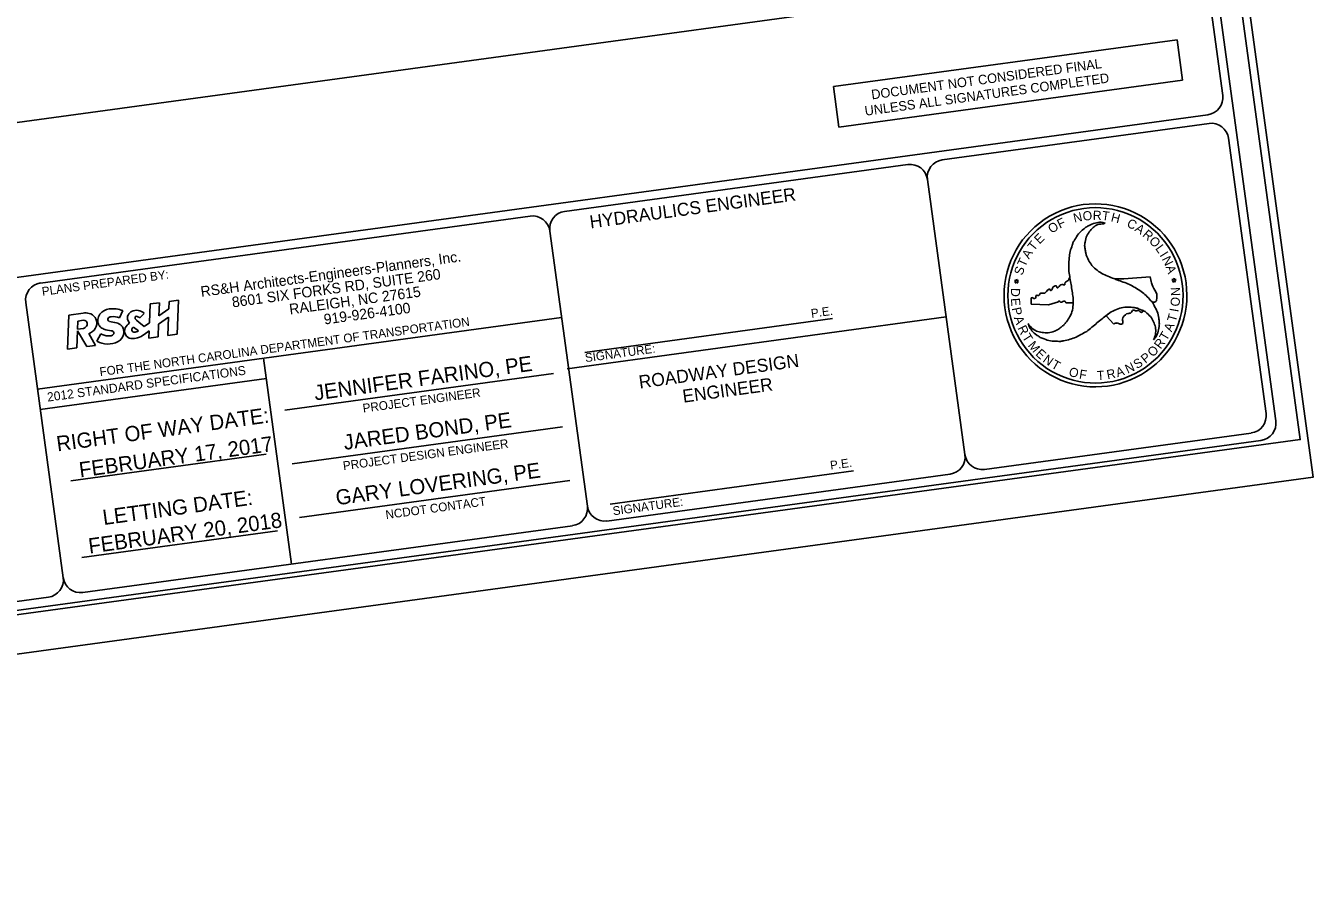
# Model space of a CAD drawing. Extents: x 2110583 to 2112764, y 580993 to 582575.
# Drawn here: x 2111873 to 2112764, y 580993 to 581578 of the extents above; entities that cross this region are included whole.
import ezdxf

# ---------------------------------------------------------------- set-up
doc = ezdxf.new("R2010")
doc.units = 0
for name, color, linetype in [('Default', 7, 'Continuous'), ('Sheet Data Field CELL', 7, 'Continuous'), ('Sheet Plot Border Inside CELL', 7, 'Continuous'), ('Sheet Plot Border Outside CELL', 7, 'Continuous'), ('Sheet Sticker Exception Certification CELL', 7, 'Continuous'), ('Sheet Title CELL', 7, 'Continuous')]:
    doc.layers.add(name, color=color, linetype=linetype)

msp = doc.modelspace()

# ---------------------------------------------------------------- linework, layer by layer
at = {"layer": 'Default'}
for p, q in [((2111958.78, 581385.98), (2111965.29, 581386.87)), ((2111965.29, 581386.87), (2111958.78, 581385.98)), ((2111965.29, 581386.87), (2111964.92, 581377.69)), ((2111964.92, 581377.69), (2111965.29, 581386.87)), ((2111971.81, 581382.67), (2111972.03, 581387.77)), ((2111972.03, 581387.77), (2111971.81, 581382.67)), ((2111972.03, 581387.77), (2111978.5, 581388.66)), ((2111978.5, 581388.66), (2111972.03, 581387.77)), ((2111978.5, 581388.66), (2111977.61, 581365.07)), ((2111977.61, 581365.07), (2111978.5, 581388.66)), ((2111901.51, 581354.72), (2111902.44, 581378.29)), ((2111902.44, 581378.29), (2111901.51, 581354.72)), ((2111902.44, 581378.29), (2111912.46, 581379.66)), ((2111912.46, 581379.66), (2111902.44, 581378.29)), ((2111937.71, 581376.35), (2111939.99, 581381.38)), ((2111954.76, 581379.5), (2111951.61, 581376.34)), ((2111951.61, 581376.34), (2111954.76, 581379.5)), ((2111958.3, 581372.99), (2111958.78, 581385.98)), ((2111958.78, 581385.98), (2111958.3, 581372.99)), ((2111964.92, 581377.69), (2111971.81, 581382.67)), ((2111971.81, 581382.67), (2111964.92, 581377.69)), ((2111908.52, 581368.56), (2111908.73, 581374.12)), ((2111908.52, 581368.56), (2111908.73, 581374.12)), ((2111912.58, 581369.12), (2111908.52, 581368.56)), ((2111912.58, 581369.12), (2111908.52, 581368.56)), ((2111908.73, 581374.12), (2111912.79, 581374.67)), ((2111908.73, 581374.12), (2111912.79, 581374.67)), ((2111950.65, 581367.45), (2111947.38, 581370.03)), ((2111947.38, 581370.03), (2111950.65, 581367.45)), ((2111949.4, 581374.78), (2111951.14, 581373.26)), ((2111951.14, 581373.26), (2111949.4, 581374.78)), ((2111951.09, 581373.31), (2111954.67, 581370.43)), ((2111951.14, 581373.26), (2111951.09, 581373.31)), ((2111954.67, 581370.43), (2111951.09, 581373.31)), ((2111951.09, 581373.31), (2111951.14, 581373.26)), ((2111954.67, 581370.43), (2111958.3, 581372.99)), ((2111958.3, 581372.99), (2111954.67, 581370.43)), ((2111964.68, 581372.07), (2111964.36, 581363.27)), ((2111964.36, 581363.27), (2111964.68, 581372.07)), ((2111971.6, 581376.96), (2111964.68, 581372.07)), ((2111964.68, 581372.07), (2111971.6, 581376.96)), ((2111971.04, 581364.18), (2111971.6, 581376.96)), ((2111971.6, 581376.96), (2111971.04, 581364.18)), ((2111908.46, 581367.49), (2111907.97, 581355.61)), ((2111907.97, 581355.61), (2111908.46, 581367.49)), ((2111914.88, 581356.5), (2111908.46, 581367.49)), ((2111908.46, 581367.49), (2111914.88, 581356.5)), ((2111916.35, 581365.44), (2111921.02, 581357.34)), ((2111921.02, 581357.34), (2111916.35, 581365.44)), ((2111924.78, 581365.21), (2111921.94, 581360.27)), ((2111925.63, 581364.83), (2111924.78, 581365.21)), ((2111928.19, 581368.2), (2111931.91, 581367.47)), ((2111958.04, 581367.31), (2111954.68, 581364.91)), ((2111954.68, 581364.91), (2111958.04, 581367.31)), ((2111957.8, 581362.37), (2111958.04, 581367.31)), ((2111958.04, 581367.31), (2111957.8, 581362.37)), ((2111964.36, 581363.27), (2111957.8, 581362.37)), ((2111957.8, 581362.37), (2111964.36, 581363.27)), ((2111977.61, 581365.07), (2111971.04, 581364.18)), ((2111971.04, 581364.18), (2111977.61, 581365.07)), ((2111907.97, 581355.61), (2111901.51, 581354.72)), ((2111901.51, 581354.72), (2111907.97, 581355.61)), ((2111921.02, 581357.34), (2111914.88, 581356.5)), ((2111914.88, 581356.5), (2111921.02, 581357.34))]:
    msp.add_line(p, q, dxfattribs=at)
msp.add_lwpolyline([(2111026.43, 581851.1), (2112527.69, 582055.98), (2112588.53, 581610.11), (2111087.27, 581405.24)], close=True, dxfattribs=at)
for centre, major_axis, ratio, start_param, end_param in [((2111914.02, 581368.21), (11.49, 1.57), 0.996622, 1.216405, 1.570796), ((2111914.02, 581368.21), (11.49, 1.57), 0.996622, 1.216405, 1.570796), ((2111915.05, 581372.79), (6.82, 0.93), 0.996622, 6.004319, 7.49959), ((2111915.05, 581372.79), (6.82, 0.93), 0.996622, 6.004319, 7.49959), ((2111929.56, 581374.66), (6.93, 0.95), 0.996622, 2.355878, 3.497187), ((2111930.94, 581373.61), (8.66, 1.18), 0.996622, 1.920759, 2.355878), ((2111932.27, 581371.1), (11.49, 1.57), 0.996622, 1.591172, 1.920764), ((2111933.2, 581365.19), (17.43, 2.38), 0.996622, 1.039775, 1.591172), ((2111947.67, 581376.5), (4.49, 0.61), 0.996622, 2.376388, 3.217137), ((2111947.67, 581376.5), (4.49, 0.61), 0.996622, 2.376388, 3.217137), ((2111948.41, 581375.96), (5.4, 0.74), 0.996622, 1.890526, 2.376388), ((2111948.41, 581375.96), (5.4, 0.74), 0.996622, 1.890526, 2.376388), ((2111949.42, 581373.92), (7.67, 1.05), 0.996622, 0.673834, 1.890526), ((2111949.42, 581373.92), (7.67, 1.05), 0.996622, 0.673834, 1.890526), ((2111912.16, 581372.21), (3.1, 0.42), 0.996622, 4.712389, 6.502592), ((2111912.16, 581372.21), (3.1, 0.42), 0.996622, 4.712389, 6.502592), ((2111913.08, 581372.55), (2.13, 0.29), 0.996622, 0.219404, 1.570796), ((2111913.08, 581372.55), (2.13, 0.29), 0.996622, 0.219404, 1.570796), ((2111914.54, 581372.86), (7.33, 1), 0.996622, 5.198251, 6.004319), ((2111914.54, 581372.86), (7.33, 1), 0.996622, 5.198251, 6.004319), ((2111928.16, 581373.92), (5.36, 0.73), 0.996622, 3.497187, 4.020151), ((2111929.86, 581376.64), (8.55, 1.17), 0.996622, 4.020151, 4.382746), ((2111930.86, 581375.27), (1.4, 0.19), 0.996622, 2.179377, 4.360808), ((2111932.13, 581373.91), (3.25, 0.44), 0.996622, 1.55325, 2.179377), ((2112049.7, 581914.14), (549.78, 75.03), 0.996622, 4.360808, 4.369952), ((2111933.16, 581365.18), (11.98, 1.63), 0.996622, 1.049808, 1.55325), ((2111934.09, 581366.04), (6.9, 0.94), 0.996622, 0.700192, 1.228359), ((2111935.83, 581367.97), (4.33, 0.59), 0.996622, 0.262985, 0.700192), ((2111931.19, 581366.02), (9.31, 1.27), 0.996622, 6.283185, 6.546171), ((2111946.37, 581367.29), (5.22, 0.71), 0.996622, 2.571961, 4.421999), ((2111946.37, 581367.29), (5.22, 0.71), 0.996622, 2.571961, 4.421999), ((2111947.81, 581366.63), (6.79, 0.93), 0.996622, 1.919932, 2.571967), ((2111947.81, 581366.63), (6.79, 0.93), 0.996622, 1.919932, 2.571961), ((2111950.01, 581377), (6.86, 0.94), 0.996622, 3.217137, 3.684768), ((2111950.01, 581377), (6.86, 0.94), 0.996622, 3.217137, 3.684768), ((2111947.74, 581368.09), (1.57, 0.21), 0.996622, 2.683953, 4.508484), ((2111947.74, 581368.09), (1.57, 0.21), 0.996622, 2.683953, 4.508484), ((2111948.78, 581367.74), (2.66, 0.36), 0.996622, 1.98337, 2.683953), ((2111948.78, 581367.74), (2.66, 0.36), 0.996622, 1.98337, 2.683953), ((2111950.64, 581375.27), (2.09, -1.89), 0.514737, 1.568464, 3.799878), ((2111950.64, 581375.27), (2.09, -1.89), 0.514737, 1.568464, 3.799878), ((2111949.49, 581376.39), (1.12, 0.15), 0.996622, 3.253305, 3.586362), ((2111949.49, 581376.39), (1.12, 0.15), 0.996622, 3.253305, 3.586362), ((2111952.61, 581378.42), (4.82, 0.66), 0.996622, 3.586362, 3.857506), ((2111952.61, 581378.42), (4.82, 0.66), 0.996622, 3.586362, 3.857506), ((2111910.43, 581378.59), (14.34, 1.96), 0.996622, 4.999066, 5.198251), ((2111910.43, 581378.59), (14.34, 1.96), 0.996622, 4.999066, 5.198251), ((2111929.6, 581373.78), (15.42, 2.1), 0.996622, 4.062862, 5.04238), ((2111930.15, 581374.95), (11, 1.5), 0.996622, 4.15812, 4.673906), ((2111930.88, 581367.47), (3.53, 0.48), 0.996622, 4.673906, 5.318308), ((2111931.18, 581363.8), (3.72, 0.51), 0.996622, 0.919817, 1.233478), ((2111932.35, 581365.86), (1.37, 0.19), 0.996622, 5.318308, 7.203003), ((2111933.33, 581366.37), (7.17, 0.98), 0.996622, 5.04238, 6.042422), ((2111933.56, 581366.34), (6.95, 0.95), 0.996622, 6.042422, 6.283185), ((2111947, 581371.26), (9.22, 1.26), 0.996622, 4.421999, 4.924513), ((2111947, 581371.26), (9.22, 1.26), 0.996622, 4.421999, 4.924513), ((2111947.93, 581370.84), (4.31, 0.59), 0.996622, 4.508484, 5.252714), ((2111947.93, 581370.84), (4.31, 0.59), 0.996622, 4.508484, 5.252714), ((2111943.79, 581380.08), (18.55, 2.53), 0.996622, 4.924513, 5.197924), ((2111943.79, 581380.08), (18.55, 2.53), 0.996622, 4.924513, 5.197924)]:
    msp.add_ellipse(centre, major_axis=major_axis, ratio=ratio, start_param=start_param, end_param=end_param, dxfattribs=at)
at = {"layer": 'Sheet Plot Border Inside CELL'}
msp.add_lwpolyline([(2110773, 581021.72), (2112754.79, 581292.17), (2112583.51, 582547.28), (2110601.71, 582276.83)], close=True, dxfattribs=at)
at = {"layer": 'Sheet Plot Border Outside CELL'}
msp.add_lwpolyline([(2112585.22, 582574.72), (2110582.61, 582301.43), (2110761.18, 580992.92), (2112763.78, 581266.21)], close=True, dxfattribs=at)
at = {"layer": 'Sheet Sticker Exception Certification CELL'}
for p, q in [((2112431.66, 581536.31), (2112669.5, 581568.76)), ((2112669.5, 581568.75), (2112673.32, 581540.81)), ((2112673.31, 581540.82), (2112435.47, 581508.37)), ((2112435.47, 581508.37), (2112431.66, 581536.31))]:
    msp.add_line(p, q, dxfattribs=at)
at = {"layer": 'Sheet Title CELL'}
for p, q in [((2111002.17, 581286.33), (2112690.83, 581516.78)), ((2112507.04, 581485.64), (2112691.64, 581510.83)), ((2112245.69, 581449.97), (2112483.26, 581482.39)), ((2112522.75, 581281.79), (2112496.77, 581472.12)), ((2111882.99, 581400.47), (2112221.91, 581446.73)), ((2112619.59, 581442.1), (2112619.48, 581441.97)), ((2112619.59, 581442.1), (2112619.48, 581441.97)), ((2112261.4, 581246.11), (2112235.42, 581436.44)), ((2112557.88, 581401.45), (2112556.99, 581402.11)), ((2112556.99, 581402.11), (2112558.1, 581402.11)), ((2112557.56, 581400.4), (2112557.88, 581401.45)), ((2112558.4, 581401.06), (2112557.56, 581400.4)), ((2112558.1, 581402.11), (2112558.4, 581403.12)), ((2112558.4, 581403.12), (2112558.77, 581402.11)), ((2112559.31, 581400.41), (2112558.4, 581401.06)), ((2112558.77, 581402.11), (2112559.86, 581402.11)), ((2112559.86, 581402.11), (2112558.96, 581401.46)), ((2112558.96, 581401.46), (2112559.31, 581400.41)), ((2112626.49, 581403.25), (2112626.49, 581403.25)), ((2112667.09, 581402.83), (2112666.01, 581402.82)), ((2112666.01, 581402.82), (2112666.91, 581402.19)), ((2112666.91, 581402.19), (2112666.59, 581401.14)), ((2112666.59, 581401.14), (2112667.43, 581401.78)), ((2112667.43, 581403.84), (2112667.09, 581402.83)), ((2112667.81, 581402.83), (2112667.43, 581403.84)), ((2112667.43, 581401.78), (2112668.32, 581401.14)), ((2112668.87, 581402.87), (2112667.81, 581402.83)), ((2112668, 581402.19), (2112668.87, 581402.87)), ((2112668.32, 581401.14), (2112668, 581402.19)), ((2111872.72, 581386.96), (2111898.69, 581196.63)), ((2112568.49, 581385.84), (2112568.61, 581389.65)), ((2112587.37, 581387.48), (2112580.49, 581385.43)), ((2112597.67, 581386.67), (2112592.66, 581386.71)), ((2112676.32, 581392.16), (2112676.32, 581392.16)), ((2112580.49, 581385.43), (2112568.49, 581385.84)), ((2112625.7, 581372.07), (2112620.37, 581377.82)), ((2112620.37, 581377.82), (2112620.37, 581377.82)), ((2112243.6, 581376.52), (2111880.89, 581327.04)), ((2112247.34, 581341.17), (2112509.76, 581376.98)), ((2112259.59, 581352.52), (2112431.13, 581375.93)), ((2112037.33, 581348.38), (2112056.75, 581206.08)), ((2112039.25, 581334.38), (2111882.8, 581313.04)), ((2111993.42, 581333.75), (2111993.42, 581333.75)), ((2112051.98, 581312.53), (2112237.88, 581337.88)), ((2112057.05, 581275.37), (2112244.26, 581300.92)), ((2112039.12, 581282.01), (2111903.85, 581263.55)), ((2111971.46, 581272.76), (2111971.46, 581272.76)), ((2112277.24, 581247.62), (2112445.52, 581270.57)), ((2112062.12, 581238.22), (2112249.33, 581263.77)), ((2112046.84, 581229.02), (2111911.57, 581210.56))]:
    msp.add_line(p, q, dxfattribs=at)
for points in [[(2112737.89, 581305.09), (2112570.68, 582530.32)], [(2112701.1, 581530.28), (2112565.55, 582523.58)], [(2112731.13, 581310.23), (2112705.16, 581500.56)], [(2110967.61, 581051.37), (2112727.62, 581291.56)], [(2112536.27, 581271.52), (2112720.86, 581296.71)], [(2112274.91, 581235.85), (2112512.48, 581268.27)], [(2111912.21, 581186.35), (2112251.13, 581232.59)], [(2111436.53, 581121.42), (2111888.43, 581183.09)]]:
    msp.add_lwpolyline(points, dxfattribs=at)
for centre, major_axis, start_param, end_param in [((2112689.2, 581528.73), (-1.62, 11.9), 3.141593, 4.712389), ((2112693.26, 581498.99), (-1.62, 11.9), 4.712389, 6.283185), ((2112508.67, 581473.74), (-1.62, 11.9), 0, 1.570796), ((2112484.88, 581470.5), (-1.62, 11.9), 4.712389, 6.283185), ((2112247.31, 581438.13), (-1.62, 11.9), 0, 1.570796), ((2112613.05, 581391.94), (8.56, -62.71), 1.43852, 4.580113), ((2112613.05, 581391.94), (8.2, -60.1), 1.43852, 4.580113), ((2112223.53, 581434.88), (-1.62, 11.9), 4.712389, 6.283185), ((2112618.85, 581736.87), (45.12, -330.63), 6.170414, 6.243823), ((2111884.61, 581388.63), (-1.62, 11.9), 0, 1.570796), ((2112618.85, 581736.87), (45.12, -330.63), 6.075485, 6.077223), ((2112613.05, 581391.94), (-8.56, 62.71), 1.43852, 4.580113), ((2112613.05, 581391.94), (-8.2, 60.1), 1.43852, 4.580113), ((2112719.23, 581308.66), (1.62, -11.9), 0, 1.570796), ((2112725.99, 581303.52), (1.62, -11.9), 0, 1.570796), ((2112510.85, 581280.23), (-1.62, 11.9), 3.141593, 4.712389), ((2112534.63, 581283.48), (1.62, -11.9), 4.712389, 6.283185), ((2112249.5, 581244.55), (-1.62, 11.9), 3.141593, 4.712389), ((2112273.29, 581247.8), (1.62, -11.9), 4.712389, 6.283185), ((2111886.8, 581195.06), (1.62, -11.9), 0, 1.570796), ((2111910.58, 581198.3), (1.62, -11.9), 4.712389, 6.283185)]:
    msp.add_ellipse(centre, major_axis=major_axis, ratio=0.999692, start_param=start_param, end_param=end_param, dxfattribs=at)
for points in [[(2112619.48, 581441.97), (2112618.05, 581442.34), (2112613.85, 581442.16), (2112609.58, 581440.77), (2112609.2, 581440.57), (2112607.07, 581439.43), (2112604.81, 581437.74), (2112601.39, 581434.48), (2112598.77, 581430.48), (2112597.73, 581428.77), (2112596.97, 581426.66), (2112595.58, 581422.19), (2112594.86, 581417.88), (2112594.6, 581412.83), (2112594.69, 581408.4), (2112595.43, 581403.88), (2112596.24, 581399.33), (2112596.91, 581394.9), (2112597.54, 581390.35), (2112597.58, 581385.83), (2112597.56, 581385.43), (2112596.77, 581380.61), (2112594.83, 581376.38), (2112592.33, 581372.83), (2112590.85, 581371.19), (2112588.74, 581369.53), (2112587.54, 581368.57), (2112584.68, 581367.1), (2112580.35, 581366.07), (2112576.11, 581366.3), (2112572.36, 581367.25), (2112569.05, 581369.35), (2112566.43, 581372.38)], [(2112653.24, 581361.25), (2112654.22, 581362.26), (2112656.19, 581366), (2112657.13, 581370.4), (2112657.19, 581370.83), (2112657.22, 581373.25), (2112656.89, 581376.08), (2112655.82, 581380.67), (2112653.61, 581384.9), (2112652.69, 581386.68), (2112651.22, 581388.42), (2112648.06, 581391.85), (2112644.69, 581394.63), (2112640.44, 581397.35), (2112636.56, 581399.46), (2112632.25, 581401.14), (2112627.94, 581402.7), (2112623.8, 581404.32), (2112619.47, 581406.06), (2112615.58, 581408.28), (2112615.26, 581408.53), (2112611.42, 581411.63), (2112608.75, 581415.43), (2112606.89, 581419.34), (2112606.29, 581421.42), (2112605.9, 581424.1), (2112605.62, 581425.64), (2112605.83, 581428.83), (2112607.09, 581433.13), (2112609.39, 581436.65), (2112612.1, 581439.41), (2112615.6, 581441.22), (2112619.48, 581441.97), (2112619.59, 581442.1)], [(2112650.92, 581404.71), (2112651.84, 581400.49), (2112654.07, 581395.52), (2112655.5, 581392.81), (2112655.47, 581390.46), (2112654.94, 581387.67), (2112652.24, 581387.38)], [(2112568.61, 581389.65), (2112568.47, 581390.01), (2112569.11, 581390.42), (2112570.89, 581389.7), (2112571.79, 581390.47), (2112571.75, 581391.24), (2112572.46, 581392.01), (2112573.68, 581391.77), (2112574.78, 581393.18), (2112575.8, 581393.43), (2112577.93, 581393.43), (2112580.46, 581395.99), (2112581.52, 581396.15), (2112581.79, 581395.47), (2112582.45, 581395.34), (2112583.53, 581397.45), (2112583.81, 581397.75), (2112585.79, 581398.54), (2112586.32, 581398.17), (2112586.47, 581397.23), (2112586.75, 581397.05), (2112587.41, 581397.52), (2112588.29, 581398.64), (2112589.91, 581399.49), (2112591.77, 581399.28), (2112592.09, 581400.8), (2112594.26, 581402.27), (2112594.7, 581403.15), (2112594.81, 581404.05)], [(2112595.41, 581404), (2112595.43, 581403.88), (2112596.24, 581399.33), (2112596.91, 581394.9), (2112597.54, 581390.35), (2112597.65, 581386.67)], [(2112652.22, 581387.36), (2112651.22, 581388.42), (2112648.06, 581391.85), (2112644.69, 581394.63), (2112640.44, 581397.35), (2112636.56, 581399.46), (2112632.25, 581401.14), (2112627.94, 581402.7), (2112626.49, 581403.25)], [(2112592.66, 581386.71), (2112592.17, 581387.63), (2112591.19, 581387.91), (2112589.88, 581387.21), (2112588.89, 581387.26), (2112587.8, 581388.04), (2112587.37, 581387.48)], [(2112566.43, 581372.38), (2112566.89, 581370.96), (2112569.13, 581367.4), (2112572.44, 581364.38), (2112572.8, 581364.19), (2112574.89, 581362.86), (2112577.48, 581361.78), (2112582.02, 581360.41), (2112586.75, 581360.2), (2112588.75, 581360.12), (2112591.06, 581360.54), (2112595.52, 581361.56), (2112599.6, 581363.06), (2112604.13, 581365.38), (2112607.88, 581367.66), (2112611.47, 581370.58), (2112614.98, 581373.58), (2112618.5, 581376.35), (2112622.15, 581379.15), (2112626.02, 581381.47), (2112626.45, 581381.64), (2112631.02, 581383.39), (2112635.6, 581383.81), (2112639.87, 581383.45), (2112642.11, 581382.99), (2112644.53, 581381.93), (2112646.05, 581381.43), (2112648.7, 581379.65), (2112651.73, 581376.42), (2112653.66, 581372.67), (2112654.72, 581368.91), (2112654.54, 581364.99), (2112653.24, 581361.25)], [(2112620.37, 581377.82), (2112622.15, 581379.15), (2112626.02, 581381.47), (2112626.45, 581381.64), (2112631.02, 581383.39), (2112635.6, 581383.81), (2112639.87, 581383.45), (2112642.11, 581382.99), (2112644.53, 581381.93), (2112645.94, 581381.45)], [(2112645.92, 581381.43), (2112645.34, 581380.32), (2112644.38, 581380.24), (2112642.71, 581381.57), (2112640.67, 581381.15), (2112639.73, 581381.69), (2112639.11, 581381.7), (2112637.63, 581379.84), (2112635.61, 581379.39), (2112632.34, 581376.96), (2112631.67, 581375.55), (2112631.92, 581372.51), (2112631.12, 581371.9), (2112630.14, 581372.05), (2112628.11, 581372.83), (2112625.7, 581372.07)]]:
    msp.add_spline(points, degree=3, dxfattribs=at)

# ---------------------------------------------------------------- texts
at = {"layer": 'Sheet Data Field CELL'}
for s, p in [('JENNIFER FARINO, PE', (2112073.03, 581319.23)), ('JARED BOND, PE', (2112093.38, 581285.02)), ('FEBRUARY 17, 2017', (2111910.37, 581265.98)), ('GARY LOVERING, PE', (2112087.96, 581246.72)), ('FEBRUARY 20, 2018', (2111916.81, 581213.32))]:
    msp.add_text(s, height=10.5053, rotation=7.77101, dxfattribs=at).set_placement(p)
at = {"layer": 'Sheet Sticker Exception Certification CELL'}
for s, p in [('DOCUMENT NOT CONSIDERED FINAL', (2112458.39, 581527.43)), ('UNLESS ALL SIGNATURES COMPLETED', (2112453.79, 581516.14))]:
    msp.add_text(s, height=6.6, rotation=7.77101, dxfattribs=at).set_placement(p)
at = {"layer": 'Sheet Title CELL'}
for s, height, rotation, p in [(' HYDRAULICS ENGINEER', 9.0044, 7.77101, (2112260.33, 581437.72)), ('N', 6.31, 13.17757, (2112598.51, 581442.16)), ('O', 6.33, 5.67716, (2112604.52, 581443.53)), ('R', 6.31, 359.06524, (2112611.16, 581444.19)), ('T', 6.33, 352.41374, (2112617.2, 581444.1)), ('H', 6.3, 345.3273, (2112623.32, 581443.24)), ('O', 6.32, 32.41639, (2112582.69, 581434.48)), ('F', 6.32, 25.26792, (2112588.34, 581438.02)), ('C', 6.29, 332.9829, (2112634.21, 581439.79)), ('A', 6.31, 325.48536, (2112639.8, 581436.9)), ('E', 6.29, 44.35752, (2112574.31, 581427.06)), ('R', 6.3, 319.12144, (2112645.14, 581433.24)), ('O', 6.32, 312.00238, (2112649.69, 581429.28)), ('A', 6.33, 58.52857, (2112567.03, 581416.68)), ('T', 6.29, 51.47352, (2112570.45, 581422.24)), ('L', 6.29, 305.7696, (2112654.19, 581424.28)), ('I', 6.32, 301.78101, (2112657.28, 581419.79)), ('RS&H Architects-Engineers-Planners, Inc.', 7.258, 7.77101, (2111994.25, 581390.84)), ('T', 6.32, 65.58019, (2112564.41, 581411.1)), ('N', 6.31, 296.08221, (2112658.87, 581417.15)), ('PLANS PREPARED BY:', 6.0484, 7.77101, (2111884.29, 581391.59)), ('8601 SIX FORKS RD, SUITE 260', 7.258, 7.77101, (2112015.91, 581383.54)), ('S', 6.3, 71.95531, (2112562.53, 581405.39)), ('A', 6.31, 288.65222, (2112661.55, 581411.57)), ('RALEIGH, NC 27615', 7.258, 7.77101, (2112055.6, 581378.71)), ('D', 6.31, 268.04808, (2112554.68, 581397.11)), ('N', 6.31, 92.40191, (2112671.73, 581391.62)), ('919-926-4100', 7.258, 7.77101, (2112079.49, 581371.71)), ('E', 6.28, 274.33408, (2112554.5, 581389.87)), ('O', 6.29, 85.15602, (2112671.15, 581384.02)), ('P.E.', 6.002, 7.77101, (2112416.58, 581376.42)), ('P', 6.31, 281.86416, (2112555.15, 581383.04)), ('T', 6.3, 74.37315, (2112668.6, 581373.15)), ('I', 6.33, 80.02175, (2112670.49, 581380.03)), ('FOR THE NORTH CAROLINA DEPARTMENT OF TRANSPORTATION', 6.0484, 7.77101, (2111924.23, 581336.01)), ('A', 6.3, 288.45477, (2112556.54, 581376.44)), ('R', 6.31, 295.5215, (2112558.98, 581369.38)), ('A', 6.32, 67.29001, (2112665.79, 581366.22)), ('T', 6.3, 302.17052, (2112562.04, 581363.12)), ('M', 6.29, 309.40432, (2112565.94, 581357.11)), ('R', 6.32, 53.10429, (2112658.11, 581354.38)), ('T', 6.29, 59.20386, (2112662.23, 581360.02)), ('SIGNATURE:', 6.002, 7.77101, (2112260.19, 581345.71)), ('ROADWAY DESIGN', 9.0037, 7.77101, (2112297.66, 581327.47)), ('E', 6.29, 316.87034, (2112571.14, 581351)), ('N', 6.32, 323.8417, (2112576.16, 581346.4)), ('P', 6.31, 39.22222, (2112647.64, 581344.55)), ('O', 6.32, 45.91493, (2112652.84, 581348.87)), ('2012 STANDARD SPECIFICATIONS', 6.243, 7.77101, (2111887.94, 581318.41)), ('T', 6.3, 330.68403, (2112581.95, 581342.25)), ('O', 6.31, 343.98969, (2112594.1, 581336.46)), ('A', 6.29, 17.78344, (2112628.26, 581335.31)), ('N', 6.29, 24.81699, (2112635.32, 581337.7)), ('S', 6.28, 32.02913, (2112641.74, 581340.82)), ('ENGINEER', 9.004, 7.77101, (2112327.89, 581317.66)), ('F', 6.3, 351.1566, (2112601.46, 581334.46)), ('T', 6.29, 4.06953, (2112614.31, 581333.3)), ('R', 6.32, 11.02828, (2112621.44, 581333.89)), ('PROJECT ENGINEER', 6.0477, 7.77101, (2112106.34, 581310.79)), ('RIGHT OF WAY DATE: ', 10.5049, 7.77101, (2111894.7, 581283.99)), ('PROJECT DESIGN ENGINEER', 6.0477, 7.77101, (2112092.67, 581271)), ('P.E.', 6.002, 7.77101, (2112429.84, 581271.35)), ('LETTING DATE:', 10.5049, 7.77101, (2111926.67, 581233.04)), ('NCDOT CONTACT', 6.0477, 7.77101, (2112122.14, 581237.18)), ('SIGNATURE:', 6.002, 7.77101, (2112279.4, 581239.79))]:
    msp.add_text(s, height=height, rotation=rotation, dxfattribs=at).set_placement(p)

doc.saveas('drawing.dxf')
